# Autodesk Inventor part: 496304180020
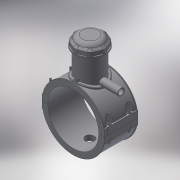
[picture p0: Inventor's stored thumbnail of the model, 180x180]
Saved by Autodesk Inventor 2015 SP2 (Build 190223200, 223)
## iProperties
Created: 2017-07
Part Number: 496304180020
Material: Generic
Description: PLASSON TAPPING SADDLE 180x20
Document SubType Name: Modeling
Designer: KIM
Mass: 1253.46 g
Surface Area: 2537.41 cm^2
Volume: 1253.46 cm^3
Density: 1 g/cm^3
Appearance: Default
Author: KIM
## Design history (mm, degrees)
derived "496304.ipt"
feature "Solid1::496304.ipt"
feature "Solid2::496304.ipt"
feature "Solid4::496304.ipt"
feature "Solid5::496304.ipt"
tag "TaggingFeature1"
body "Solid1"
body "Solid2"
other parameters: "d2" = 219, "d3" = 45, "d4" = 118, "d5" = 0, "d6" = 0.1, "d8" = 0, "d19" = 6, "d20" = 6, "d21" = 70.8, "d23" = 0, "d24" = 35.4, "d26" = 0, "d29" = 3, "d31" = 6, "d32" = 0, "d33" = 0, "d34" = 0.6, "d40" = 106.704, "d41" = 72, "d43" = 0, "d45" = 0, "d47" = 173.4, "d70" = 15, "d72" = 0, "d73" = 6, "d75" = 5, "d76" = 0, "d77" = 9, "d79" = 15, "d80" = 47.2, "d82" = 5 deg, "d84" = 4, "d85" = 14, "d86" = 0, "d87" = 3, "d88" = 0, "d89" = 1, "d90" = 1, "d91" = 94.4, "d92" = 0, "d93" = 0.5, "d94" = 94.73684, "d96" = 209.304, "d97" = 2.36, "d98" = 0, "d102" = 1.8, "d120" = 140 deg, "d121" = 24.228, "d122" = 20 deg, "d123" = 410.4, "d124" = 123.12, "d126" = 0, "d143" = 185.4, "d145" = 19.38462, "d149" = 2.7, "d150" = 21.32308, "d153" = 118, "d154" = 0, "d156" = 102.6, "d157" = 160 deg, "d159" = 5.04, "d161" = 2.7, "d162" = 70.8, "d163" = 0, "d167" = 18, "d168" = 100.09756, "d170" = 3.375, "d172" = 0, "d173" = 1, "d176" = 20 deg, "d177" = 12.6, "d178" = 25.2, "d180" = 0, "d183" = 10.08, "d184" = 10.08, "d185" = 38.35, "d186" = 38.35, "d187" = 102.6, "d188" = 7.56, "d189" = 12.6, "d190" = 0, "d191" = 153.9, "d193" = 6.3, "d194" = 4.13, "d195" = 90 deg, "d197" = 0, "d199" = 0, "d200" = 12.6, "d202" = 0, "d203" = 177, "d204" = 68.4, "d205" = 50.4, "d206" = 61.2, "d207" = 132.75, "d208" = 138.06, "d209" = 164.61, "d210" = 61.92, "d211" = 72, "d212" = 57.6, "d213" = 36, "d216" = 0, "d217" = 18, "d218" = 18, "d219" = 3.6, "d224" = 0, "d230" = 3.6, "d233" = 6, "d236" = 109.5, "d237" = 35.4, "d238" = 6.02433, "d240" = 35.4, "d241" = 35.4, "d242" = 35.4, "d243" = 6, "d244" = 35.4, "d245" = 35.4, "d246" = 35.4, "d247" = 6, "d248" = 6, "d249" = 6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
